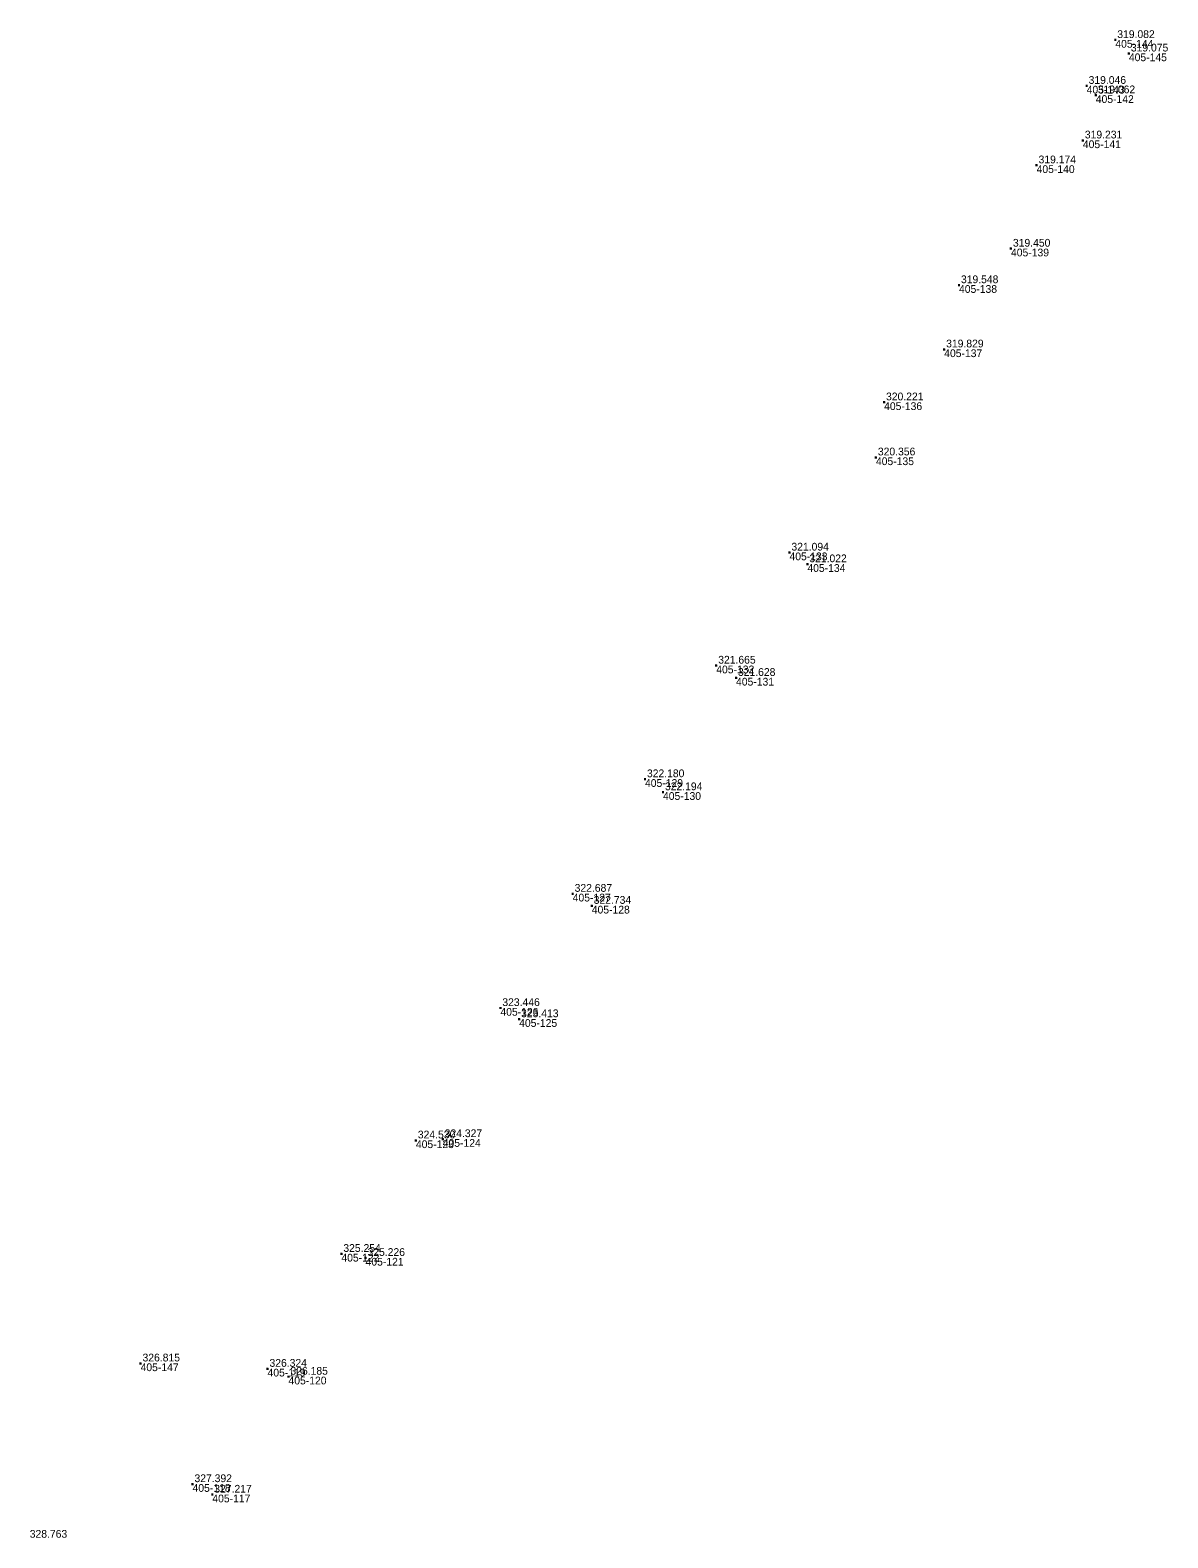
# Model space of a CAD drawing. Extents: x -829398 to -819400, y -1074439 to -1067977.
# Drawn here: x -826017.1 to -825840.9, y -1069130.3 to -1068896.8 of the extents above; entities that cross this region are included whole.
import ezdxf

# ---------------------------------------------------------------- set-up
doc = ezdxf.new("R2010")
doc.units = 0
for name, color, linetype in [('Vrstva 60', 7, 'Continuous'), ('Vrstva 61', 7, 'Continuous'), ('Čísla bodů_doměření_2012', 7, 'Continuous')]:
    doc.layers.add(name, color=color, linetype=linetype)

# ---------------------------------------------------------------- blocks, each defined once
blk = doc.blocks.new('BOD')
at = {"layer": 'Čísla bodů_doměření_2012'}
for p, q in [((-0.15, 0), (0.15, 0)), ((0, -0.15), (0, 0.15))]:
    blk.add_line(p, q, dxfattribs=at)

msp = doc.modelspace()

# ---------------------------------------------------------------- block references
at = {"layer": 'Vrstva 60'}
for p in [(-825849.045, -1068898.358), (-825846.944, -1068900.443), (-825853.486, -1068905.458), (-825852.074, -1068906.914), (-825854.071, -1068913.909), (-825861.239, -1068917.761), (-825865.208, -1068930.668), (-825873.259, -1068936.322), (-825875.551, -1068946.268), (-825884.865, -1068954.462), (-825886.126, -1068962.992), (-825899.519, -1068977.727), (-825896.747, -1068979.532), (-825910.862, -1068995.235), (-825907.799, -1068997.134), (-825921.9, -1069012.825), (-825919.112, -1069014.837), (-825933.1, -1069030.567), (-825930.146, -1069032.43), (-825944.297, -1069048.258), (-825941.394, -1069049.987), (-825957.386, -1069068.755), (-825953.23, -1069068.558), (-825968.929, -1069086.328), (-825965.181, -1069086.954), (-826000.031, -1069103.293), (-825980.368, -1069104.123), (-825977.121, -1069105.349), (-825991.984, -1069121.985), (-825988.918, -1069123.613)]:
    msp.add_blockref('BOD', p, dxfattribs=at)

# ---------------------------------------------------------------- texts
for s, p in [('405-144', (-825849.045, -1068899.558)), ('405-145', (-825846.944, -1068901.643)), ('405-143', (-825853.486, -1068906.658)), ('405-142', (-825852.074, -1068908.114)), ('405-141', (-825854.071, -1068915.109)), ('405-140', (-825861.239, -1068918.961)), ('405-139', (-825865.208, -1068931.868)), ('405-138', (-825873.259, -1068937.522)), ('405-137', (-825875.551, -1068947.468)), ('405-136', (-825884.865, -1068955.662)), ('405-135', (-825886.126, -1068964.192)), ('405-133', (-825899.519, -1068978.927)), ('405-134', (-825896.747, -1068980.732)), ('405-132', (-825910.862, -1068996.435)), ('405-131', (-825907.799, -1068998.334)), ('405-129', (-825921.9, -1069014.025)), ('405-130', (-825919.112, -1069016.037)), ('405-127', (-825933.1, -1069031.767)), ('405-128', (-825930.146, -1069033.63)), ('405-126', (-825944.297, -1069049.458)), ('405-125', (-825941.394, -1069051.187)), ('405-123', (-825957.386, -1069069.955)), ('405-124', (-825953.23, -1069069.758)), ('405-122', (-825968.929, -1069087.528)), ('405-121', (-825965.181, -1069088.154)), ('405-147', (-826000.031, -1069104.493)), ('405-119', (-825980.368, -1069105.323)), ('405-120', (-825977.121, -1069106.549)), ('405-118', (-825991.984, -1069123.185)), ('405-117', (-825988.918, -1069124.813))]:
    msp.add_text(s, height=1.2, dxfattribs=at).set_placement(p)
at = {"layer": 'Vrstva 61'}
for s, p in [('319.082', (-825848.745, -1068898.058)), ('319.075', (-825846.644, -1068900.143)), ('319.046', (-825853.186, -1068905.158)), ('319.062', (-825851.774, -1068906.614)), ('319.231', (-825853.771, -1068913.609)), ('319.174', (-825860.939, -1068917.461)), ('319.450', (-825864.908, -1068930.368)), ('319.548', (-825872.959, -1068936.022)), ('319.829', (-825875.251, -1068945.968)), ('320.221', (-825884.565, -1068954.162)), ('320.356', (-825885.826, -1068962.692)), ('321.094', (-825899.219, -1068977.427)), ('321.022', (-825896.447, -1068979.232)), ('321.665', (-825910.562, -1068994.935)), ('321.628', (-825907.499, -1068996.834)), ('322.180', (-825921.6, -1069012.525)), ('322.194', (-825918.812, -1069014.537)), ('322.687', (-825932.8, -1069030.267)), ('322.734', (-825929.846, -1069032.13)), ('323.446', (-825943.997, -1069047.958)), ('323.413', (-825941.094, -1069049.687)), ('324.530', (-825957.086, -1069068.455)), ('324.327', (-825952.93, -1069068.258)), ('325.254', (-825968.629, -1069086.028)), ('325.226', (-825964.881, -1069086.654)), ('326.815', (-825999.731, -1069102.993)), ('326.324', (-825980.068, -1069103.823)), ('326.185', (-825976.821, -1069105.049)), ('327.392', (-825991.684, -1069121.685)), ('327.217', (-825988.618, -1069123.313)), ('328.763', (-826017.202, -1069130.294))]:
    msp.add_text(s, height=1.2, dxfattribs=at).set_placement(p)

doc.saveas('drawing.dxf')
